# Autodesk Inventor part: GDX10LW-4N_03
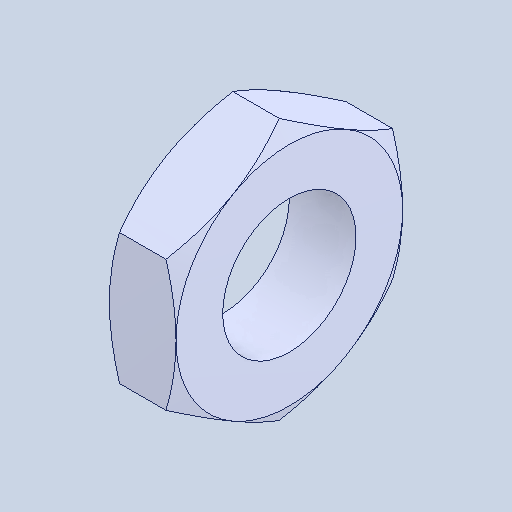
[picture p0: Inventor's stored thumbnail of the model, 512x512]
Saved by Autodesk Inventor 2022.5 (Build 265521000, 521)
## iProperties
Created: 2024-06
Part Number: GDX10LW-4N_03
Material: 一般
Document SubType Name: Modeling
Designer: ImaoCorp
Density: 1 g/cm^3
Appearance: 既定
Author: ImaoCorp
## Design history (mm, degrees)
feature "GDX10LW-4N_03"
node "ソリッド1"
